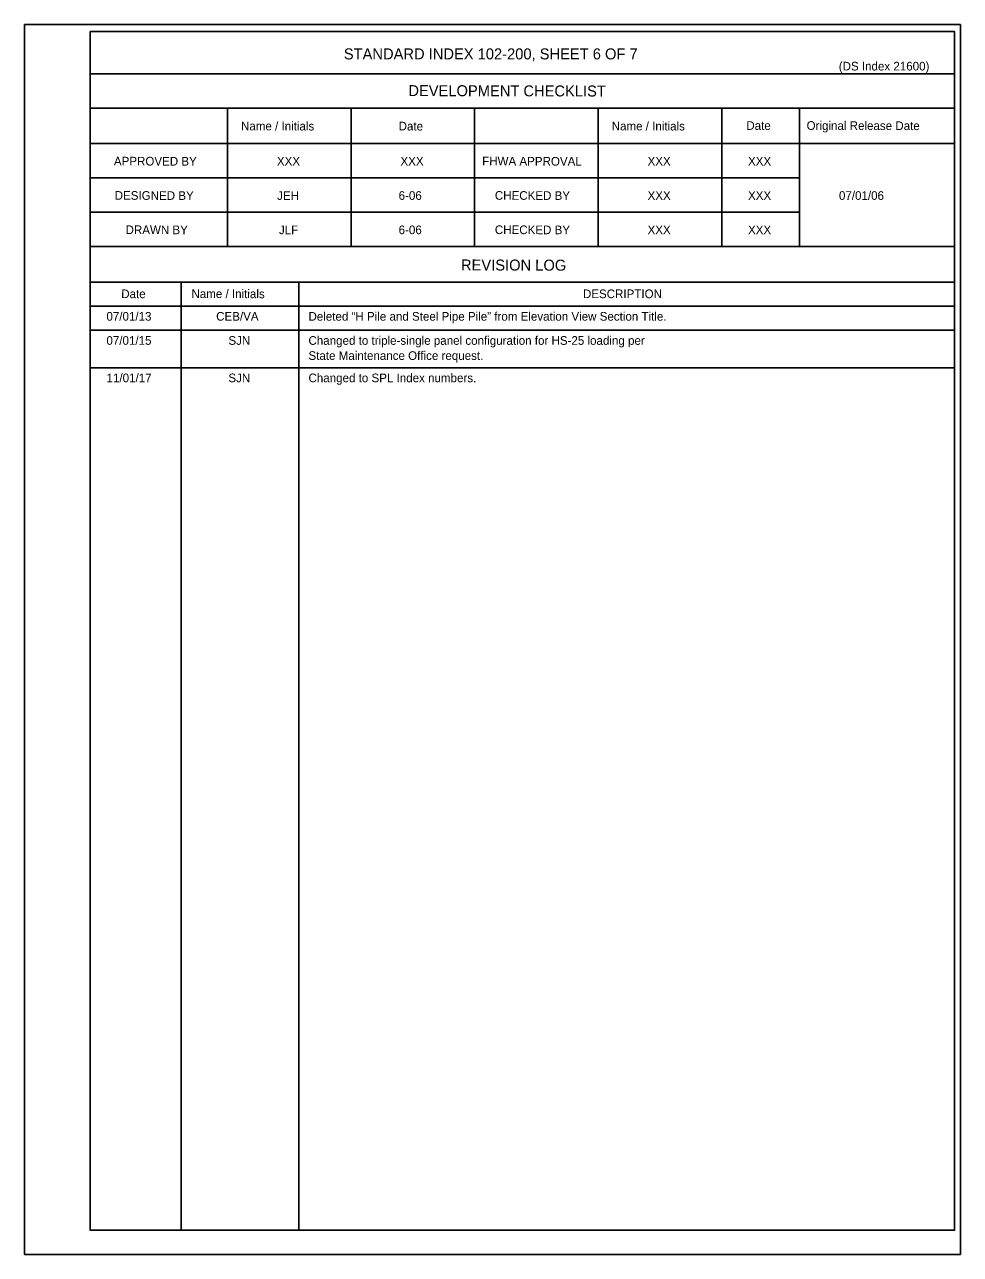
# Model space of a CAD drawing. Extents: x 112363.6 to 112390.2, y 109543.2 to 109558.
# Drawn here: x 112382.02 to 112390.2, y 109546.47 to 109557.22 of the extents above; entities that cross this region are included whole.
import ezdxf

# ---------------------------------------------------------------- set-up
doc = ezdxf.new("R2010")
doc.units = 0
for name, color, linetype in [('Border', 7, 'Continuous'), ('PlotBorder_dp', 7, 'Continuous'), ('TextStructures', 7, 'Continuous')]:
    doc.layers.add(name, color=color, linetype=linetype)

msp = doc.modelspace()

# ---------------------------------------------------------------- linework, layer by layer
at = {"layer": 'Border'}
for p, q in [((112390.147, 109556.792), (112382.592, 109556.792)), ((112390.147, 109556.492), (112382.592, 109556.492)), ((112383.792, 109556.492), (112383.792, 109555.282)), ((112384.872, 109556.492), (112384.872, 109555.282)), ((112385.952, 109556.492), (112385.952, 109555.282)), ((112387.032, 109556.492), (112387.032, 109555.282)), ((112388.112, 109556.492), (112388.112, 109555.282)), ((112388.793, 109556.492), (112388.793, 109555.282)), ((112390.147, 109556.182), (112382.592, 109556.182)), ((112388.793, 109555.882), (112382.592, 109555.882)), ((112388.793, 109555.582), (112382.592, 109555.582)), ((112390.147, 109555.282), (112382.592, 109555.282)), ((112390.147, 109554.971), (112382.592, 109554.971)), ((112383.388, 109554.971), (112383.388, 109546.682)), ((112384.416, 109554.971), (112384.416, 109546.682)), ((112390.147, 109554.76), (112382.592, 109554.76))]:
    msp.add_line(p, q, dxfattribs=at)
msp.add_lwpolyline([(112382.593, 109557.16), (112390.147, 109557.16), (112390.147, 109546.682), (112382.593, 109546.682)], close=True, dxfattribs=at)
at = {"layer": 'PlotBorder_dp'}
msp.add_line((112382.019, 109546.471), (112382.019, 109546.471), dxfattribs=at)
msp.add_lwpolyline([(112382.019, 109557.221), (112390.199, 109557.221), (112390.199, 109546.471), (112382.019, 109546.471)], close=True, dxfattribs=at)
at = {"layer": 'TextStructures'}
for p, q in [((112382.592, 109554.549), (112390.147, 109554.549)), ((112382.592, 109554.222), (112390.147, 109554.222))]:
    msp.add_line(p, q, dxfattribs=at)

# ---------------------------------------------------------------- texts
for s, height, p in [('STANDARD INDEX 102-200, SHEET 6 OF 7', 0.096, (112384.809, 109556.917)), ('(DS Index 21600)', 0.0756, (112389.135, 109556.82)), ('XXX', 0.0756, (112384.224, 109555.989)), ('XXX', 0.0756, (112385.304, 109555.989)), ('XXX', 0.0756, (112387.464, 109555.989)), ('XXX', 0.0756, (112388.342, 109555.989)), ('JEH', 0.0756, (112384.226, 109555.689)), ('6-06', 0.0756, (112385.288, 109555.689)), ('XXX', 0.0756, (112387.464, 109555.689)), ('XXX', 0.0756, (112388.342, 109555.689)), ('07/01/06', 0.0756, (112389.137, 109555.689)), ('JLF', 0.0756, (112384.242, 109555.389)), ('6-06', 0.0756, (112385.288, 109555.389)), ('XXX', 0.0756, (112387.464, 109555.389)), ('XXX', 0.0756, (112388.342, 109555.389)), ('DESCRIPTION', 0.0756, (112386.899, 109554.83)), ('07/01/13', 0.0756, (112382.734, 109554.633)), ('CEB/VA', 0.0756, (112383.693, 109554.633)), ('Deleted “H Pile and Steel Pipe Pile” from Elevation View Section Title.', 0.0756, (112384.5, 109554.633)), ('07/01/15', 0.0756, (112382.734, 109554.422)), ('SJN', 0.0756, (112383.8, 109554.422)), ('Changed to triple-single panel configuration for HS-25 loading per', 0.0756, (112384.5, 109554.422)), ('State Maintenance Office request.', 0.0756, (112384.5, 109554.29)), ('11/01/17', 0.0756, (112382.735, 109554.095)), ('SJN', 0.0756, (112383.8, 109554.095)), ('Changed to SPL Index numbers.', 0.0756, (112384.5, 109554.095))]:
    msp.add_text(s, height=height, dxfattribs=at).set_placement(p)
for s, height, p in [('DEVELOPMENT CHECKLIST', 0.096, (112385.373, 109556.596)), ('Name / Initials', 0.0756, (112383.91, 109556.297)), ('Date', 0.0756, (112385.288, 109556.296)), ('Name / Initials', 0.0756, (112387.15, 109556.297)), ('Date', 0.0756, (112388.327, 109556.301)), ('Original Release Date', 0.0756, (112388.854, 109556.301)), ('APPROVED BY', 0.0756, (112382.799, 109555.99)), ('FHWA APPROVAL', 0.0756, (112386.018, 109555.99)), ('DESIGNED BY', 0.0756, (112382.806, 109555.69)), ('CHECKED BY', 0.0756, (112386.129, 109555.69)), ('DRAWN BY', 0.0756, (112382.901, 109555.39)), ('CHECKED BY', 0.0756, (112386.129, 109555.39)), ('REVISION LOG', 0.096, (112385.833, 109555.072)), ('Date', 0.0756, (112382.863, 109554.83)), ('Name / Initials', 0.0756, (112383.477, 109554.831))]:
    msp.add_text(s, height=height, rotation=359.8756, dxfattribs=at).set_placement(p)

doc.saveas('drawing.dxf')
